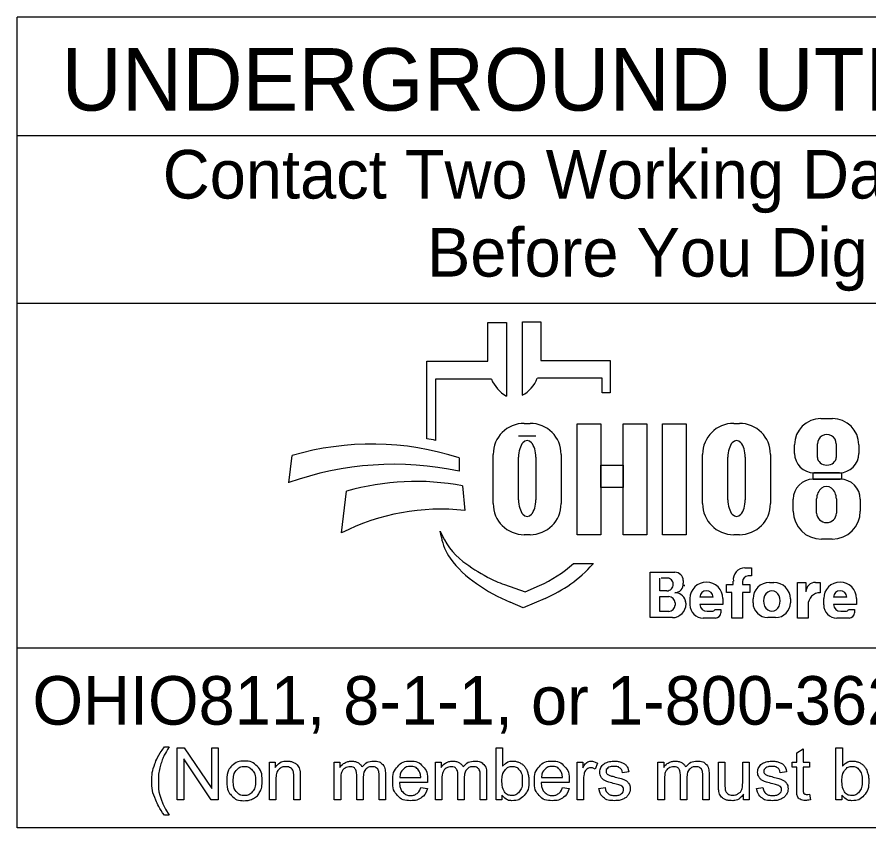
# Model space of a CAD drawing. Extents: x 0 to 34, y 0 to 22.
# Drawn here: x 2.378 to 4.831, y 2.143 to 4.48 of the extents above; entities that cross this region are included whole.
import ezdxf

# ---------------------------------------------------------------- set-up
doc = ezdxf.new("R2010")
doc.units = 0
doc.layers.add('SH_Data', color=7, linetype='Continuous')
doc.layers.add('SH_Text', color=7, linetype='Continuous')

msp = doc.modelspace()

# ---------------------------------------------------------------- linework, layer by layer
at = {"layer": 'SH_Data'}
for p, q in [((2.3775, 2.1428), (2.3775, 4.4803)), ((6.6275, 4.4803), (2.3775, 4.4803)), ((2.3775, 4.1387), (6.6275, 4.1387)), ((2.3775, 3.6553), (6.6275, 3.6553)), ((6.6275, 2.6607), (2.3775, 2.6607)), ((6.6275, 2.1428), (2.3775, 2.1428))]:
    msp.add_line(p, q, dxfattribs=at)
at = {"layer": 'SH_Text'}
for p, q in [((3.7335, 3.4883), (3.7335, 3.5998)), ((3.7335, 3.5998), (3.7872, 3.5998)), ((3.7872, 3.5998), (3.7872, 3.3877)), ((3.8329, 3.39), (3.8329, 3.6021)), ((3.8329, 3.6021), (3.8865, 3.6021)), ((3.8865, 3.6021), (3.8865, 3.4906)), ((3.5576, 3.2644), (3.5576, 3.4883)), ((3.5576, 3.4883), (3.7335, 3.4883)), ((3.8865, 3.4906), (4.0857, 3.4906)), ((4.0857, 3.4906), (4.0857, 3.3968)), ((3.5828, 3.4369), (3.5828, 3.26)), ((3.7439, 3.4369), (3.5828, 3.4369)), ((4.0625, 3.4392), (3.8761, 3.4392)), ((4.0625, 3.3968), (4.0625, 3.4392)), ((4.0857, 3.3968), (4.0625, 3.3968)), ((4.6931, 3.3231), (4.7258, 3.3231)), ((3.8385, 3.3091), (3.8551, 3.3091)), ((4.4416, 3.3091), (4.4581, 3.3091)), ((3.8718, 3.2721), (3.822, 3.2721)), ((4.6168, 3.2225), (4.6168, 3.2468)), ((4.683, 3.2111), (4.683, 3.2504)), ((4.7371, 3.2504), (4.7371, 3.2111)), ((4.8022, 3.2468), (4.8022, 3.2225)), ((3.1602, 3.1381), (3.1696, 3.2162)), ((3.7491, 3.0776), (3.7491, 3.2196)), ((3.9445, 3.2196), (3.9445, 3.0776)), ((4.3521, 3.0776), (4.3521, 3.2196)), ((4.5476, 3.2196), (4.5476, 3.0776)), ((3.6509, 3.2097), (3.6509, 3.1709)), ((3.822, 3.089), (3.822, 3.2114)), ((3.8718, 3.2114), (3.8718, 3.089)), ((4.425, 3.089), (4.425, 3.2114)), ((4.4748, 3.2114), (4.4748, 3.089)), ((4.7462, 3.1665), (4.6728, 3.1665)), ((4.671, 3.1482), (4.7483, 3.1482)), ((3.6608, 3.1291), (3.6671, 3.0582)), ((3.312, 2.9936), (3.3267, 3.1137)), ((4.6131, 3.0563), (4.6131, 3.0903)), ((4.6806, 3.0503), (4.6806, 3.0912)), ((4.7374, 3.0912), (4.7374, 3.0503)), ((4.8062, 3.0903), (4.8062, 3.0563)), ((3.5997, 2.9807), (3.5967, 2.9986)), ((3.8551, 2.9882), (3.8385, 2.9882)), ((4.4581, 2.9882), (4.4416, 2.9882)), ((4.7252, 2.9753), (4.6941, 2.9753)), ((3.98, 2.9048), (4.0375, 2.9048)), ((4.2013, 2.749), (4.2013, 2.8798)), ((4.2013, 2.8798), (4.2725, 2.8798)), ((4.4739, 2.8926), (4.4934, 2.8926)), ((4.4934, 2.8926), (4.4934, 2.8696)), ((4.2293, 2.8263), (4.2293, 2.8632)), ((4.2545, 2.8632), (4.2332, 2.8632)), ((4.2963, 2.856), (4.2963, 2.8481)), ((4.4406, 2.8442), (4.4406, 2.8546)), ((4.4667, 2.8526), (4.4667, 2.8442)), ((4.4934, 2.8691), (4.4832, 2.8691)), ((4.5451, 2.8508), (4.5573, 2.8508)), ((4.6254, 2.7478), (4.6254, 2.8505)), ((4.6254, 2.8505), (4.6499, 2.8505)), ((4.6499, 2.8505), (4.6499, 2.8237)), ((4.6772, 2.8505), (4.691, 2.8505)), ((4.691, 2.8505), (4.691, 2.8209)), ((3.7816, 2.8444), (3.841, 2.8239)), ((3.841, 2.8239), (3.8821, 2.8417)), ((4.2487, 2.8263), (4.2293, 2.8263)), ((4.4213, 2.8212), (4.4213, 2.8442)), ((4.4213, 2.8442), (4.4406, 2.8442)), ((4.4667, 2.8442), (4.4883, 2.8442)), ((4.4883, 2.8442), (4.4883, 2.8212)), ((3.8983, 2.8044), (3.835, 2.7769)), ((4.2293, 2.7669), (4.2293, 2.8097)), ((4.2293, 2.8097), (4.2548, 2.8097)), ((4.3159, 2.7858), (4.3159, 2.8042)), ((4.3824, 2.8082), (4.3439, 2.8082)), ((4.4104, 2.8042), (4.4104, 2.7866)), ((4.4362, 2.8212), (4.4213, 2.8212)), ((4.4362, 2.7478), (4.4362, 2.8212)), ((4.4883, 2.8212), (4.4667, 2.8212)), ((4.4667, 2.8212), (4.4667, 2.7478)), ((4.4973, 2.7922), (4.4973, 2.8029)), ((4.6051, 2.8029), (4.6051, 2.7922)), ((4.7008, 2.7858), (4.7008, 2.8042)), ((4.7674, 2.8082), (4.7288, 2.8082)), ((4.7953, 2.8042), (4.7953, 2.7866)), ((3.835, 2.7769), (3.7976, 2.7934)), ((4.2729, 2.7916), (4.2729, 2.7853)), ((4.3043, 2.7887), (4.3043, 2.7884)), ((4.4104, 2.7866), (4.344, 2.7866)), ((4.3876, 2.7729), (4.4045, 2.7729)), ((4.4045, 2.7729), (4.4045, 2.7631)), ((4.6559, 2.786), (4.6559, 2.7478)), ((4.7953, 2.7866), (4.7289, 2.7866)), ((4.7725, 2.7729), (4.7894, 2.7729)), ((4.7894, 2.7729), (4.7894, 2.7631)), ((4.265, 2.749), (4.2013, 2.749)), ((4.2546, 2.7669), (4.2293, 2.7669)), ((4.3649, 2.7673), (4.379, 2.7673)), ((4.5623, 2.7494), (4.5401, 2.7494)), ((4.7498, 2.7673), (4.7639, 2.7673)), ((4.3892, 2.7478), (4.3538, 2.7478)), ((4.4667, 2.7478), (4.4362, 2.7478)), ((4.6559, 2.7478), (4.6254, 2.7478)), ((4.7742, 2.7478), (4.7388, 2.7478))]:
    msp.add_line(p, q, dxfattribs=at)
for points in [[(3.991, 3.3081), (4.0589, 3.3081), (4.0589, 2.9881), (3.991, 2.9881)], [(4.1231, 3.3081), (4.1911, 3.3081), (4.1911, 2.9881), (4.1231, 2.9881)], [(4.2364, 3.3081), (4.3052, 3.3081), (4.3052, 2.9881), (4.2364, 2.9881)], [(4.0589, 3.1882), (4.1231, 3.1882), (4.1231, 3.1242), (4.0589, 3.1242)], [(4.6706, 3.1665), (4.7523, 3.1665), (4.7523, 3.1481), (4.6706, 3.1481)]]:
    msp.add_lwpolyline(points, close=True, dxfattribs=at)
for points in [[(2.8021, 2.3766), (2.8153, 2.3766)], [(2.8389, 2.2239), (2.8389, 2.3741), (2.8592, 2.3741), (2.9382, 2.2561), (2.9382, 2.3741), (2.9572, 2.3741), (2.9572, 2.2239), (2.9369, 2.2239), (2.8579, 2.3419), (2.8579, 2.2239), (2.8389, 2.2239)], [(3.7743, 2.2239), (3.7573, 2.2239), (3.7573, 2.3741), (3.7757, 2.3741), (3.7757, 2.3206)], [(4.6233, 2.2558), (4.6233, 2.3185), (4.6097, 2.3185), (4.6097, 2.3328), (4.6233, 2.3328), (4.6233, 2.3597), (4.6417, 2.3708), (4.6417, 2.3328), (4.6601, 2.3328), (4.6601, 2.3185), (4.6417, 2.3185), (4.6417, 2.2547)], [(4.7534, 2.2239), (4.7363, 2.2239), (4.7363, 2.3741), (4.7548, 2.3741), (4.7548, 2.3206)], [(3.1048, 2.2239), (3.1048, 2.3328), (3.1214, 2.3328), (3.1214, 2.3173)], [(3.2912, 2.2239), (3.2912, 2.3328), (3.3077, 2.3328), (3.3077, 2.3174)], [(3.5826, 2.2239), (3.5826, 2.3328), (3.5991, 2.3328), (3.5991, 2.3174)], [(3.9904, 2.2239), (3.9904, 2.3328), (4.007, 2.3328), (4.007, 2.3163)], [(4.2236, 2.2239), (4.2236, 2.3328), (4.2401, 2.3328), (4.2401, 2.3174)], [(4.3979, 2.2654), (4.3979, 2.3328), (4.4164, 2.3328), (4.4164, 2.2724)], [(4.4676, 2.2745), (4.4676, 2.3328), (4.4861, 2.3328), (4.4861, 2.2239), (4.4696, 2.2239)], [(4.0495, 2.3293), (4.043, 2.3122)], [(3.1233, 2.2833), (3.1233, 2.2239), (3.1048, 2.2239)], [(3.1932, 2.2908), (3.1932, 2.2239), (3.1748, 2.2239), (3.1748, 2.2901)], [(3.3743, 2.2871), (3.3743, 2.2239), (3.3559, 2.2239), (3.3559, 2.2946)], [(3.4388, 2.2986), (3.4388, 2.2239), (3.4203, 2.2239), (3.4203, 2.2924)], [(3.4799, 2.2887), (3.5406, 2.2887)], [(3.6657, 2.2871), (3.6657, 2.2239), (3.6473, 2.2239), (3.6473, 2.2946)], [(3.7301, 2.2986), (3.7301, 2.2239), (3.7117, 2.2239), (3.7117, 2.2924)], [(3.8879, 2.2887), (3.9486, 2.2887)], [(4.1394, 2.3046), (4.1213, 2.3022)], [(4.3067, 2.2871), (4.3067, 2.2239), (4.2883, 2.2239), (4.2883, 2.2946)], [(4.3711, 2.2986), (4.3711, 2.2239), (4.3527, 2.2239), (4.3527, 2.2924)], [(4.594, 2.3046), (4.5759, 2.3022)], [(3.3097, 2.2803), (3.3097, 2.2239), (3.2912, 2.2239)], [(3.56, 2.2736), (3.4788, 2.2736)], [(3.5404, 2.2591), (3.5595, 2.2567)], [(3.601, 2.2803), (3.601, 2.2239), (3.5826, 2.2239)], [(3.968, 2.2736), (3.8868, 2.2736)], [(3.9484, 2.2591), (3.9675, 2.2567)], [(4.0088, 2.2809), (4.0088, 2.2239), (3.9904, 2.2239)], [(4.053, 2.2564), (4.0712, 2.2593)], [(4.242, 2.2803), (4.242, 2.2239), (4.2236, 2.2239)], [(4.5076, 2.2564), (4.5258, 2.2593)], [(3.7743, 2.2375), (3.7743, 2.2239)], [(4.4696, 2.2239), (4.4696, 2.24)], [(4.6601, 2.2404), (4.6628, 2.2241)], [(4.7534, 2.2375), (4.7534, 2.2239)], [(2.8153, 2.1798), (2.8021, 2.1798)]]:
    msp.add_lwpolyline(points, dxfattribs=at)
for centre, radius, start, end in [((3.8353, 3.4736), 0.0985, 201.9296, 240.7469), ((3.7847, 3.476), 0.0985, 299.2531, 338.0704), ((4.6931, 3.2468), 0.0763, 90, 180), ((4.7258, 3.2468), 0.0763, 0, 90), ((3.8385, 3.2196), 0.0895, 90, 180), ((3.8551, 3.2196), 0.0895, 0, 90), ((4.4416, 3.2196), 0.0895, 90, 180), ((4.4581, 3.2196), 0.0895, 0, 90), ((3.4295, 2.4554), 0.8191, 79.2074, 81.0007), ((3.3997, 2.4302), 0.8191, 72.1402, 106.3144), ((4.6728, 3.2225), 0.056, 180, 270), ((4.7462, 3.2225), 0.056, 270, 0), ((3.4628, 2.2991), 0.8919, 77.8238, 109.8274), ((3.5267, 2.4094), 0.7322, 79.44, 105.8467), ((4.671, 3.0903), 0.0579, 90, 180), ((4.7483, 3.0903), 0.0579, 0, 90), ((3.8385, 3.0776), 0.0895, 180, 270), ((3.8551, 3.0776), 0.0895, 270, 0), ((4.4416, 3.0776), 0.0895, 180, 270), ((4.4581, 3.0776), 0.0895, 270, 0), ((3.5987, 2.4262), 0.6357, 83.8248, 116.8021), ((4.6941, 3.0563), 0.081, 180, 270), ((4.7252, 3.0563), 0.081, 270, 0), ((3.7841, 3.0707), 0.2008, 201.0457, 232.5314), ((3.741, 3.0048), 0.1433, 189.6817, 216.0884), ((3.8747, 3.1022), 0.3088, 216.0884, 235.7167), ((3.9766, 3.3219), 0.5173, 232.5314, 241.794), ((3.7387, 3.1722), 0.3602, 293.4582, 312.0712), ((3.7387, 3.1722), 0.401, 293.4582, 317.8286), ((4.2725, 2.856), 0.0238, 0, 90), ((4.4739, 2.859), 0.0335, 90, 187.5187), ((4.0412, 3.3465), 0.6044, 235.7167, 246.2325), ((3.8914, 3.1631), 0.3371, 241.794, 250.9821), ((4.2505, 2.8463), 0.0169, 357.8325, 90), ((4.2721, 2.8453), 0.0243, 270, 6.6529), ((4.3631, 2.8042), 0.0473, 0, 180), ((4.4832, 2.8526), 0.0165, 90, 180), ((4.5451, 2.8029), 0.0478, 90, 180), ((4.5573, 2.8029), 0.0478, 0, 90), ((4.6768, 2.8237), 0.0269, 89.2449, 180), ((4.7481, 2.8042), 0.0473, 0, 180), ((4.2487, 2.845), 0.0187, 270, 2.0582), ((4.2827, 2.8438), 0.0175, 347.4023, 0), ((4.3632, 2.8072), 0.0193, 2.9632, 177.0368), ((4.7481, 2.8072), 0.0193, 2.9632, 177.0368), ((4.2548, 2.7916), 0.0181, 0, 90), ((4.2722, 2.7889), 0.0321, 4.0748, 90), ((4.6908, 2.786), 0.0349, 89.6033, 180), ((4.2546, 2.7853), 0.0184, 270, 0), ((4.265, 2.7884), 0.0393, 270, 0), ((4.2714, 2.7887), 0.033, 0, 11.7502), ((4.3538, 2.7858), 0.038, 180, 270), ((4.3649, 2.7883), 0.021, 184.827, 270), ((4.379, 2.7767), 0.00938, 270, 335.9979), ((4.5401, 2.7922), 0.0428, 180, 270), ((4.5623, 2.7922), 0.0428, 270, 0), ((4.7388, 2.7858), 0.038, 180, 270), ((4.7498, 2.7883), 0.021, 184.827, 270), ((4.7639, 2.7767), 0.00938, 270, 335.9979), ((4.3892, 2.7631), 0.0152, 270, 0), ((4.7742, 2.7631), 0.0152, 270, 0)]:
    msp.add_arc(centre, radius, start, end, dxfattribs=at)
for centre, major_axis, ratio, start_param, end_param in [((4.71, 3.2504), (0.0271, 0), 0.969373, 0, 3.141593), ((3.8469, 3.2114), (0, 0.0484), 0.514403, 4.712389, 7.853982), ((4.4499, 3.2114), (0, 0.0484), 0.514403, 4.712389, 7.853982), ((4.71, 3.2111), (0.0271, 0), 0.818453, 3.141593, 6.283185), ((4.709, 3.0912), (0, 0.0358), 0.794529, 4.712389, 7.853982), ((3.8469, 3.089), (0, 0.0484), 0.514403, 1.570796, 4.712389), ((4.4499, 3.089), (0, 0.0484), 0.514403, 1.570796, 4.712389), ((4.709, 3.0503), (0.0284, 0), 0.959837, 3.141593, 6.283185), ((4.5517, 2.7976), (0, 0.029), 0.832186, 4.712389, 7.853982), ((4.5517, 2.7976), (0, 0.0302), 0.797287, 1.570796, 4.712389)]:
    msp.add_ellipse(centre, major_axis=major_axis, ratio=ratio, start_param=start_param, end_param=end_param, dxfattribs=at)
for points in [[(2.8021, 2.1798), (2.7869, 2.199), (2.7763, 2.2248), (2.7657, 2.2506), (2.7657, 2.2783), (2.7657, 2.3026), (2.7736, 2.325), (2.7829, 2.3509), (2.8021, 2.3766)], [(2.8153, 2.3766), (2.8029, 2.3553), (2.7989, 2.3462), (2.7927, 2.332), (2.7891, 2.3167), (2.7847, 2.2975), (2.7847, 2.2782), (2.7847, 2.2289), (2.8153, 2.1798)], [(2.9814, 2.2783), (2.9814, 2.3085), (2.9981, 2.3231), (3.0122, 2.3352), (3.0323, 2.3352), (3.0547, 2.3352), (3.069, 2.3205), (3.0832, 2.3058), (3.0832, 2.2799), (3.0832, 2.2589), (3.0769, 2.2469), (3.0706, 2.2348), (3.0586, 2.2282), (3.0466, 2.2215), (3.0323, 2.2215), (3.0095, 2.2215), (2.9954, 2.2362), (2.9814, 2.2508), (2.9814, 2.2783)], [(3.1214, 2.3173), (3.1334, 2.3352), (3.156, 2.3352), (3.1659, 2.3352), (3.1741, 2.3316), (3.1823, 2.3281), (3.1864, 2.3224), (3.1905, 2.3166), (3.1922, 2.3087), (3.1932, 2.3036), (3.1932, 2.2908)], [(3.3077, 2.3174), (3.3128, 2.3254), (3.3214, 2.3303), (3.3299, 2.3352), (3.3407, 2.3352), (3.3528, 2.3352), (3.3606, 2.3301), (3.3683, 2.3251), (3.3715, 2.3161), (3.3844, 2.3352), (3.4051, 2.3352), (3.4213, 2.3352), (3.43, 2.3262), (3.4388, 2.3172), (3.4388, 2.2986)], [(3.5595, 2.2567), (3.555, 2.24), (3.5428, 2.2307), (3.5306, 2.2215), (3.5117, 2.2215), (3.4878, 2.2215), (3.4738, 2.2362), (3.4598, 2.2509), (3.4598, 2.2774), (3.4598, 2.3049), (3.474, 2.32), (3.4881, 2.3352), (3.5106, 2.3352), (3.5324, 2.3352), (3.5463, 2.3203), (3.5601, 2.3055), (3.5601, 2.2785), (3.5601, 2.2769), (3.56, 2.2736)], [(3.5991, 2.3174), (3.6042, 2.3254), (3.6127, 2.3303), (3.6212, 2.3352), (3.6321, 2.3352), (3.6442, 2.3352), (3.6519, 2.3301), (3.6597, 2.3251), (3.6628, 2.3161), (3.6758, 2.3352), (3.6965, 2.3352), (3.7127, 2.3352), (3.7214, 2.3262), (3.7301, 2.3172), (3.7301, 2.2986)], [(3.7757, 2.3206), (3.7874, 2.3352), (3.8055, 2.3352), (3.8155, 2.3352), (3.8245, 2.3311), (3.8335, 2.3271), (3.8392, 2.3198), (3.845, 2.3124), (3.8483, 2.3021), (3.8516, 2.2918), (3.8516, 2.28), (3.8516, 2.252), (3.8378, 2.2368), (3.8239, 2.2215), (3.8046, 2.2215), (3.7853, 2.2215), (3.7743, 2.2375)], [(3.9675, 2.2567), (3.963, 2.24), (3.9508, 2.2307), (3.9386, 2.2215), (3.9196, 2.2215), (3.8958, 2.2215), (3.8818, 2.2362), (3.8678, 2.2509), (3.8678, 2.2774), (3.8678, 2.3049), (3.882, 2.32), (3.8961, 2.3352), (3.9186, 2.3352), (3.9404, 2.3352), (3.9543, 2.3203), (3.9681, 2.3055), (3.9681, 2.2785), (3.9681, 2.2769), (3.968, 2.2736)], [(4.007, 2.3163), (4.0133, 2.3278), (4.0187, 2.3315), (4.0241, 2.3352), (4.0305, 2.3352), (4.0398, 2.3352), (4.0495, 2.3293)], [(4.0712, 2.2593), (4.0727, 2.2483), (4.0798, 2.2425), (4.0868, 2.2366), (4.0995, 2.2366), (4.1122, 2.2366), (4.1184, 2.2418), (4.1245, 2.247), (4.1245, 2.254), (4.1245, 2.2602), (4.1191, 2.2638), (4.1153, 2.2663), (4.1002, 2.2701), (4.0799, 2.2752), (4.072, 2.2789), (4.0642, 2.2827), (4.0601, 2.2893), (4.0561, 2.2959), (4.0561, 2.3038), (4.0561, 2.3111), (4.0594, 2.3173), (4.0628, 2.3235), (4.0685, 2.3276), (4.0728, 2.3308), (4.0803, 2.333), (4.0877, 2.3352), (4.0962, 2.3352), (4.109, 2.3352), (4.1187, 2.3315), (4.1284, 2.3278), (4.133, 2.3215), (4.1377, 2.3152), (4.1394, 2.3046)], [(4.2401, 2.3174), (4.2452, 2.3254), (4.2537, 2.3303), (4.2622, 2.3352), (4.2731, 2.3352), (4.2852, 2.3352), (4.2929, 2.3301), (4.3007, 2.3251), (4.3038, 2.3161), (4.3168, 2.3352), (4.3375, 2.3352), (4.3537, 2.3352), (4.3624, 2.3262), (4.3711, 2.3172), (4.3711, 2.2986)], [(4.5258, 2.2593), (4.5273, 2.2483), (4.5343, 2.2425), (4.5414, 2.2366), (4.554, 2.2366), (4.5668, 2.2366), (4.5729, 2.2418), (4.5791, 2.247), (4.5791, 2.254), (4.5791, 2.2602), (4.5736, 2.2638), (4.5698, 2.2663), (4.5548, 2.2701), (4.5345, 2.2752), (4.5266, 2.2789), (4.5188, 2.2827), (4.5147, 2.2893), (4.5107, 2.2959), (4.5107, 2.3038), (4.5107, 2.3111), (4.514, 2.3173), (4.5173, 2.3235), (4.5231, 2.3276), (4.5274, 2.3308), (4.5348, 2.333), (4.5423, 2.3352), (4.5508, 2.3352), (4.5636, 2.3352), (4.5733, 2.3315), (4.583, 2.3278), (4.5876, 2.3215), (4.5922, 2.3152), (4.594, 2.3046)], [(4.7548, 2.3206), (4.7664, 2.3352), (4.7846, 2.3352), (4.7946, 2.3352), (4.8036, 2.3311), (4.8125, 2.3271), (4.8183, 2.3198), (4.8241, 2.3124), (4.8274, 2.3021), (4.8306, 2.2918), (4.8306, 2.28), (4.8306, 2.252), (4.8168, 2.2368), (4.803, 2.2215), (4.7836, 2.2215), (4.7644, 2.2215), (4.7534, 2.2375)], [(3.0003, 2.2783), (3.0003, 2.2574), (3.0094, 2.247), (3.0185, 2.2366), (3.0323, 2.2366), (3.046, 2.2366), (3.0551, 2.2471), (3.0642, 2.2575), (3.0642, 2.279), (3.0642, 2.2991), (3.0551, 2.3095), (3.0459, 2.3199), (3.0323, 2.3199), (3.0185, 2.3199), (3.0094, 2.3096), (3.0003, 2.2992), (3.0003, 2.2783)], [(3.1748, 2.2901), (3.1748, 2.3013), (3.1726, 2.3069), (3.1705, 2.3125), (3.165, 2.3158), (3.1595, 2.3191), (3.1521, 2.3191), (3.1404, 2.3191), (3.1318, 2.3117), (3.1233, 2.3042), (3.1233, 2.2833)], [(3.3559, 2.2946), (3.3559, 2.3069), (3.3514, 2.313), (3.3469, 2.3191), (3.3366, 2.3191), (3.3288, 2.3191), (3.3222, 2.315), (3.3156, 2.311), (3.3126, 2.3031), (3.3097, 2.2952), (3.3097, 2.2803)], [(3.4203, 2.2924), (3.4203, 2.3035), (3.4185, 2.3083), (3.4168, 2.3132), (3.412, 2.3162), (3.4073, 2.3191), (3.401, 2.3191), (3.3895, 2.3191), (3.3819, 2.3115), (3.3743, 2.3039), (3.3743, 2.2871)], [(3.5406, 2.2887), (3.5394, 2.3025), (3.5337, 2.3094), (3.5249, 2.3201), (3.5108, 2.3201), (3.4981, 2.3201), (3.4894, 2.3115), (3.4808, 2.303), (3.4799, 2.2887)], [(3.6473, 2.2946), (3.6473, 2.3069), (3.6428, 2.313), (3.6383, 2.3191), (3.628, 2.3191), (3.6202, 2.3191), (3.6136, 2.315), (3.607, 2.311), (3.604, 2.3031), (3.601, 2.2952), (3.601, 2.2803)], [(3.7117, 2.2924), (3.7117, 2.3035), (3.7099, 2.3083), (3.7081, 2.3132), (3.7034, 2.3162), (3.6987, 2.3191), (3.6923, 2.3191), (3.6809, 2.3191), (3.6733, 2.3115), (3.6657, 2.3039), (3.6657, 2.2871)], [(3.7741, 2.2792), (3.7741, 2.2596), (3.7794, 2.2509), (3.7881, 2.2366), (3.8029, 2.2366), (3.815, 2.2366), (3.8238, 2.2471), (3.8326, 2.2576), (3.8326, 2.2784), (3.8326, 2.2998), (3.8241, 2.3099), (3.8157, 2.3201), (3.8038, 2.3201), (3.7917, 2.3201), (3.7829, 2.3096), (3.7741, 2.299), (3.7741, 2.2792)], [(3.9486, 2.2887), (3.9474, 2.3025), (3.9417, 2.3094), (3.9328, 2.3201), (3.9188, 2.3201), (3.9061, 2.3201), (3.8974, 2.3115), (3.8888, 2.303), (3.8879, 2.2887)], [(4.043, 2.3122), (4.0363, 2.3162), (4.0295, 2.3162), (4.0235, 2.3162), (4.0187, 2.3125), (4.0139, 2.3089), (4.0119, 2.3024), (4.0088, 2.2926), (4.0088, 2.2809)], [(4.1213, 2.3022), (4.1201, 2.3106), (4.1142, 2.3153), (4.1083, 2.3201), (4.0975, 2.3201), (4.0848, 2.3201), (4.0794, 2.3159), (4.0739, 2.3116), (4.0739, 2.306), (4.0739, 2.3024), (4.0762, 2.2995), (4.0785, 2.2966), (4.0833, 2.2946), (4.086, 2.2936), (4.0996, 2.2899), (4.1192, 2.2847), (4.1269, 2.2813), (4.1347, 2.278), (4.1391, 2.2717), (4.1435, 2.2653), (4.1435, 2.2559), (4.1435, 2.2467), (4.1381, 2.2386), (4.1327, 2.2304), (4.1226, 2.226), (4.1124, 2.2215), (4.0996, 2.2215), (4.0784, 2.2215), (4.0672, 2.2303), (4.0561, 2.2391), (4.053, 2.2564)], [(4.2883, 2.2946), (4.2883, 2.3069), (4.2838, 2.313), (4.2793, 2.3191), (4.269, 2.3191), (4.2612, 2.3191), (4.2546, 2.315), (4.248, 2.311), (4.245, 2.3031), (4.242, 2.2952), (4.242, 2.2803)], [(4.3527, 2.2924), (4.3527, 2.3035), (4.3509, 2.3083), (4.3491, 2.3132), (4.3444, 2.3162), (4.3397, 2.3191), (4.3333, 2.3191), (4.3219, 2.3191), (4.3143, 2.3115), (4.3067, 2.3039), (4.3067, 2.2871)], [(4.5759, 2.3022), (4.5747, 2.3106), (4.5688, 2.3153), (4.5629, 2.3201), (4.5521, 2.3201), (4.5394, 2.3201), (4.5339, 2.3159), (4.5285, 2.3116), (4.5285, 2.306), (4.5285, 2.3024), (4.5308, 2.2995), (4.533, 2.2966), (4.5378, 2.2946), (4.5406, 2.2936), (4.5542, 2.2899), (4.5737, 2.2847), (4.5815, 2.2813), (4.5893, 2.278), (4.5937, 2.2717), (4.5981, 2.2653), (4.5981, 2.2559), (4.5981, 2.2467), (4.5927, 2.2386), (4.5873, 2.2304), (4.5772, 2.226), (4.567, 2.2215), (4.5542, 2.2215), (4.5329, 2.2215), (4.5218, 2.2303), (4.5107, 2.2391), (4.5076, 2.2564)], [(4.7532, 2.2792), (4.7532, 2.2596), (4.7585, 2.2509), (4.7672, 2.2366), (4.782, 2.2366), (4.7941, 2.2366), (4.8029, 2.2471), (4.8116, 2.2576), (4.8116, 2.2784), (4.8116, 2.2998), (4.8032, 2.3099), (4.7948, 2.3201), (4.7828, 2.3201), (4.7708, 2.3201), (4.762, 2.3096), (4.7532, 2.299), (4.7532, 2.2792)], [(3.4788, 2.2736), (3.4799, 2.2557), (3.489, 2.2462), (3.4981, 2.2366), (3.5117, 2.2366), (3.5219, 2.2366), (3.5291, 2.242), (3.5362, 2.2473), (3.5404, 2.2591)], [(3.8868, 2.2736), (3.8879, 2.2557), (3.897, 2.2462), (3.9061, 2.2366), (3.9197, 2.2366), (3.9299, 2.2366), (3.937, 2.242), (3.9442, 2.2473), (3.9484, 2.2591)], [(4.4696, 2.24), (4.4569, 2.2215), (4.4351, 2.2215), (4.4255, 2.2215), (4.4171, 2.2252), (4.4088, 2.2289), (4.4047, 2.2345), (4.4007, 2.2401), (4.3991, 2.2482), (4.3979, 2.2536), (4.3979, 2.2654)], [(4.4164, 2.2724), (4.4164, 2.258), (4.4175, 2.253), (4.4192, 2.2457), (4.4249, 2.2416), (4.4305, 2.2374), (4.4388, 2.2374), (4.4471, 2.2374), (4.4543, 2.2417), (4.4616, 2.2459), (4.4646, 2.2533), (4.4676, 2.2606), (4.4676, 2.2745)], [(4.6628, 2.2241), (4.655, 2.2224), (4.6488, 2.2224), (4.6388, 2.2224), (4.6333, 2.2256), (4.6278, 2.2288), (4.6255, 2.234), (4.6233, 2.2392), (4.6233, 2.2558)], [(4.6417, 2.2547), (4.6417, 2.2468), (4.6427, 2.2445), (4.6436, 2.2423), (4.6458, 2.2409), (4.648, 2.2396), (4.6521, 2.2396), (4.6551, 2.2396), (4.6601, 2.2404)]]:
    msp.add_open_spline(points, degree=3, dxfattribs=at)

# ---------------------------------------------------------------- texts
for s, height, p in [('UNDERGROUND UTILITIES', 0.18, (2.5057, 4.2106)), ('Contact Two Working Days', 0.14, (2.7972, 3.9571)), ('Before You Dig', 0.14, (3.5583, 3.7321)), ('OHIO811, 8-1-1, or 1-800-362-2764', 0.14, (2.422, 2.4406))]:
    msp.add_text(s, height=height, dxfattribs=at).set_placement(p)

doc.saveas('drawing.dxf')
